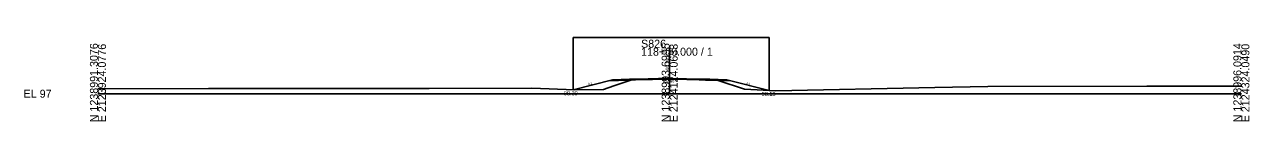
# Model space of a CAD drawing. Extents: x 2119282 to 2119710, y 1215030 to 1220057.
# Drawn here: x 2119281.9 to 2119710.4, y 1216530.1 to 1216559.4 of the extents above; entities that cross this region are included whole.
import ezdxf

# ---------------------------------------------------------------- set-up
doc = ezdxf.new("R2010")
doc.units = 0
for name, color, linetype in [('XS_CELL', 7, 'Continuous'), ('XS_M_DITCH', 7, 'Continuous'), ('XS_P_FINISHED_GRADE', 7, 'Continuous'), ('XS_P_FINISHED_GRADE_ELEV_TX', 7, 'Continuous'), ('XS_P_SUBGRADE_GRANULAR', 7, 'Continuous'), ('XS_P_SUBGRADE_PAVEMENT', 7, 'Continuous'), ('XS_P_TX_DCH', 7, 'Continuous'), ('XS_P_TX_FS_BS', 7, 'Continuous'), ('XS_X_GROUND', 7, 'Continuous'), ('XS_X_GROUND_TX', 7, 'Continuous')]:
    doc.layers.add(name, color=color, linetype=linetype)

msp = doc.modelspace()

# ---------------------------------------------------------------- linework, layer by layer
at = {"layer": 'XS_CELL'}
for p, q in [((2119507.6, 1216539.8), (2119507.6, 1216555.91)), ((2119307.6, 1216539.8), (2119507.6, 1216539.8)), ((2119507.6, 1216539.8), (2119707.6, 1216539.8))]:
    msp.add_line(p, q, dxfattribs=at)
at = {"layer": 'XS_M_DITCH'}
for p, q in [((2119473.79, 1216541.19), (2119473.79, 1216559.44)), ((2119473.79, 1216559.44), (2119542.42, 1216559.44)), ((2119542.42, 1216540.94), (2119542.42, 1216559.44))]:
    msp.add_line(p, q, dxfattribs=at)
at = {"layer": 'XS_P_FINISHED_GRADE'}
for p, q in [((2119487.6, 1216544.64), (2119473.79, 1216541.19)), ((2119493.6, 1216544.88), (2119487.6, 1216544.64)), ((2119495.6, 1216544.92), (2119493.6, 1216544.88)), ((2119507.6, 1216545.16), (2119495.6, 1216544.92)), ((2119507.6, 1216545.16), (2119519.6, 1216544.92)), ((2119519.6, 1216544.92), (2119521.6, 1216544.88)), ((2119521.6, 1216544.88), (2119527.6, 1216544.64)), ((2119527.6, 1216544.64), (2119542.42, 1216540.94))]:
    msp.add_line(p, q, dxfattribs=at)
at = {"layer": 'XS_P_SUBGRADE_GRANULAR'}
for p, q in [((2119493.17, 1216544.58), (2119486.25, 1216544.3)), ((2119522.04, 1216544.58), (2119528.95, 1216544.3))]:
    msp.add_line(p, q, dxfattribs=at)
at = {"layer": 'XS_P_SUBGRADE_PAVEMENT'}
for p, q in [((2119493.6, 1216544.88), (2119493.17, 1216544.58)), ((2119495.61, 1216544.63), (2119493.17, 1216544.58)), ((2119507.6, 1216544.87), (2119495.61, 1216544.63)), ((2119507.6, 1216544.87), (2119519.6, 1216544.63)), ((2119519.6, 1216544.63), (2119522.04, 1216544.58)), ((2119521.6, 1216544.88), (2119522.04, 1216544.58))]:
    msp.add_line(p, q, dxfattribs=at)
at = {"layer": 'XS_X_GROUND'}
for p, q in [((2119488.13, 1216542.61), (2119494.34, 1216544.71)), ((2119494.34, 1216544.71), (2119496.11, 1216544.9)), ((2119496.11, 1216544.9), (2119496.46, 1216544.94)), ((2119496.46, 1216544.94), (2119503.68, 1216545.08)), ((2119503.68, 1216545.08), (2119507.6, 1216545.16)), ((2119507.6, 1216545.16), (2119508.17, 1216545.17)), ((2119508.17, 1216545.17), (2119513.37, 1216544.9)), ((2119513.37, 1216544.9), (2119520.19, 1216544.55)), ((2119520.19, 1216544.55), (2119521.57, 1216544.51)), ((2119521.57, 1216544.51), (2119524.56, 1216544.39)), ((2119524.56, 1216544.39), (2119533.78, 1216541.37)), ((2119307.6, 1216541.51), (2119346.23, 1216541.57)), ((2119346.23, 1216541.57), (2119365.52, 1216541.59)), ((2119365.52, 1216541.59), (2119423.46, 1216541.68)), ((2119423.46, 1216541.68), (2119459.33, 1216541.74)), ((2119459.33, 1216541.74), (2119474.48, 1216541.17)), ((2119474.48, 1216541.17), (2119484.45, 1216541.33)), ((2119484.45, 1216541.33), (2119488.13, 1216542.61)), ((2119533.78, 1216541.37), (2119544.76, 1216540.82)), ((2119544.76, 1216540.82), (2119600.36, 1216541.94)), ((2119600.36, 1216541.94), (2119618.9, 1216542.31)), ((2119618.9, 1216542.31), (2119674.53, 1216542.44)), ((2119674.53, 1216542.44), (2119685.26, 1216542.46)), ((2119685.26, 1216542.46), (2119688.86, 1216542.48)), ((2119688.86, 1216542.48), (2119697.5, 1216542.44)), ((2119697.5, 1216542.44), (2119707.6, 1216542.41))]:
    msp.add_line(p, q, dxfattribs=at)

# ---------------------------------------------------------------- texts
at = {"layer": 'XS_CELL'}
for s, p in [('N 1238991.3076', (2119307.6, 1216529.8)), ('E 2123924.0776', (2119310.4, 1216529.8)), ('N 1238993.6995', (2119507.6, 1216529.8)), ('E 2124124.0633', (2119510.4, 1216529.8)), ('N 1238996.0914', (2119707.6, 1216529.8)), ('E 2124324.0490', (2119710.4, 1216529.8))]:
    msp.add_text(s, height=2.8, rotation=90, dxfattribs=at).set_placement(p)
for s, p in [('S826', (2119497.6, 1216555.91)), ('118+00.000 / 1', (2119497.6, 1216553.11)), ('EL 97', (2119281.6, 1216538.4))]:
    msp.add_text(s, height=2.8, dxfattribs=at).set_placement(p)
at = {"layer": 'XS_P_FINISHED_GRADE_ELEV_TX'}
msp.add_text('102.36', height=1.25, rotation=90, dxfattribs=at).set_placement((2119507.45, 1216547.04))
at = {"layer": 'XS_P_TX_DCH'}
for s, p in [('98.39', (2119470.61, 1216539.24)), ('98.13', (2119539.8, 1216539.02))]:
    msp.add_text(s, height=1.4, dxfattribs=at).set_placement(p)
at = {"layer": 'XS_P_TX_FS_BS'}
for rotation, p in [(14.015, (2119479.11, 1216542.76)), (345.9638, (2119534.27, 1216543.13))]:
    msp.add_text('4:1', height=0.8, rotation=rotation, dxfattribs=at).set_placement(p)
at = {"layer": 'XS_X_GROUND_TX'}
msp.add_text('102.36', height=1, dxfattribs=at).set_placement((2119505.03, 1216543.75))

doc.saveas('drawing.dxf')
